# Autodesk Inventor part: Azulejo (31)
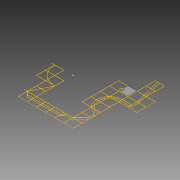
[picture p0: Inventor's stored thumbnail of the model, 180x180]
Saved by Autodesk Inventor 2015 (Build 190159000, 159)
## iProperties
Created: 2015-04
Part Number: Azulejo (31)
Material: Genérico
Document SubType Name: Modeling
Designer: Felipe
Density: 1 g/cm^3
Appearance: Padrão
Author: Felipe
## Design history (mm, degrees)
sketch "Sketch1"
  geometry: L1 (-1510, -7490)-(-1510, -6010); L2 (-3010, -1490)-(-3010, -10); L3 (-2990, 10)-(-1510, 10); L4 (-1510, -10)-(-2990, -10); L5 (-1510, -1490)-(-1510, -10); L6 (-1490, -10)-(-1490, -1490); L7 (-1490, -1490)-(-10, -1490); L8 (-10, -1510)-(-1490, -1510); L9 (-10, -2990)-(-10, -1510); L10 (-10, -5990)-(-10, -4510); L11 (-1490, -7490)-(-10, -7490); L12 (4490, -6010)-(3010, -6010); L13 (10, -1510)-(10, -2990); L14 (10, -3010)-(10, -4490); L15 (10, -4510)-(10, -5990); L16 (10, -5990)-(1490, -5990); L17 (1490, -6010)-(10, -6010); L18 (10, -7490)-(1490, -7490); L19 (1510, -5990)-(2990, -5990); L20 (2990, -6010)-(1510, -6010); L21 (1510, -7490)-(2990, -7490); L22 (4490, 1510)-(4490, 2990); L23 (4490, 10)-(4490, 1490); L24 (4490, -1490)-(4490, -10); L25 (4490, -2990)-(4490, -1510); L26 (3010, -5990)-(4490, -5990); L27 (3010, -7490)-(4490, -7490); L28 (4510, 3010)-(5990, 3010); L29 (5990, 2990)-(4510, 2990); L30 (4510, 2990)-(4510, 1510); L31 (4510, 1510)-(5990, 1510); L32 (5990, 1510)-(5990, 1740.185); L33 (5990, 1760.2)-(5990, 2259.8); L34 (5990, 2279.815)-(5990, 2990); L35 (5990, 1490)-(4510, 1490); L36 (4510, 1490)-(4510, 10); L37 (4510, 10)-(5990, 10); L38 (5990, 10)-(5990, 1490); L39 (5975.983, -10)-(4510, -10); L40 (4510, -10)-(4510, -1490); L41 (5990, -1510)-(5782.897, -1510); L42 (5782.897, -1510)-(5688.66, -1510); L43 (5668.66, -1510)-(5482.895, -1510); L44 (5482.895, -1510)-(5388.656, -1510); L45 (5368.656, -1510)-(4510, -1510); L46 (4510, -1510)-(4510, -2990); L47 (4510, -2990)-(5975.983, -2990); L48 (5990, -2975.728)-(5990, -2837.377); L49 (5990, -2837.377)-(5990, -2536.247); L50 (5990, -2500.476)-(5990, -2317.632); L51 (5990, -2317.632)-(5990, -1510); L52 (5990, -3010)-(4510, -3010); L53 (5990, -4490)-(5990, -3010); L54 (4510, -5990)-(5990, -5990); L55 (5990, -5990)-(5990, -4510); L56 (4510, -7490)-(5990, -7490); L57 (5990, -7490)-(5990, -6310); L58 (5990, -6290)-(5990, -6010); L59 (7490, 4510)-(7490, 5990); L60 (6010, 3010)-(7490, 3010); L61 (7490, 3010)-(7490, 4490); L62 (7490, 2990)-(6010, 2990); L63 (6010, 2990)-(6010, 2279.815); L64 (6010, 2259.8)-(6010, 1760.2)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; A1 r 250 centre (6000, 2010) between (5990, 2259.8) and (5990, 1760.2); A2 r 250 centre (6000, 2010) between (6010, 1760.2) and (6010, 2259.8); A3 r 270 centre (6000, 2010) between (5990, 2279.815) and (5990, 1740.185); A4 r 270 centre (6000, 2010) between (6010, 1740.185) and (6010, 2279.815); A5 r 3010.017 centre (0, 0) between (-1490, -2615.358) and (-346.554, -2990); A6 r 2990.017 centre (0, 0) between (-1490, -2592.316) and (-10, -2990); A7 r 3010.017 centre (0, 0) between (-2603.863, -1510) and (-1510, -2603.863); A8 r 2990.017 centre (0, 0) between (-2580.717, -1510) and (-1510, -2580.717); A9 r 3010.017 centre (0, 0) between (-2990, -346.554) and (-2615.358, -1490); A10 r 2990.017 centre (0, 0) between (-2990, -10) and (-2592.316, -1490); A11 r 2131.367 centre (7500, -1500) between (7490, 631.344) and (6010, 24.017); A12 r 2131.367 centre (7500, -1500) between (5975.983, -10) and (5368.656, -1490); A13 r 2131.367 centre (7500, -1500) between (5368.656, -1510) and (5975.983, -2990); A14 r 2131.367 centre (7500, -1500) between (6010, -3024.017) and (7190, -3608.703); A15 r 1831.367 centre (7500, -1500) between (7490.321, 331.342) and (6463.753, 10); A16 r 1831.367 centre (7500, -1500) between (6435.196, -10) and (6010, -435.196); A17 r 1831.367 centre (7500, -1500) between (5990, -463.753) and (5668.66, -1490); A18 r 1831.367 centre (7500, -1500) between (5668.66, -1510) and (5990, -2536.247); A19 r 1831.367 centre (7500, -1500) between (6010, -2564.804) and (6435.196, -2990); A20 r 1831.367 centre (7500, -1500) between (6463.753, -3010) and (7490, -3331.34); A21 r 2111.367 centre (7500, -1500) between (7490.047, 611.344) and (6024.272, 10); A22 r 2111.367 centre (7500, -1500) between (5990, -24.272) and (5388.656, -1490); A23 r 2111.367 centre (7500, -1500) between (5388.656, -1510) and (5990, -2975.728); A24 r 2111.367 centre (7500, -1500) between (6024.272, -3010) and (7210, -3591.357); A25 r 1811.367 centre (7500, -1500) between (7490.374, 311.342) and (6499.524, 10); A26 r 1811.367 centre (7500, -1500) between (6469.975, -10) and (6010, -469.975); A27 r 1811.367 centre (7500, -1500) between (5990, -499.524) and (5688.66, -1490); A28 r 1811.367 centre (7500, -1500) between (5688.66, -1510) and (5990, -2500.476); A29 r 1811.367 centre (7500, -1500) between (6010, -2530.025) and (6469.975, -2990); A30 r 1811.367 centre (7500, -1500) between (6499.524, -3010) and (7490, -3311.34); A31 r 449.871 centre (7499.449, -4060.672) between (7510, -4510.419) and (7521.546, -4510); 9 further points
  constraints: 698 end point, 64 point on circle, 31 centre point, 11 point on line, 1 other
extrude "Extrusion1" new body sketch "Sketch1" distance "d0" = 60; taper "d1" = 0 deg
extrude "Extrusion2" new body sketch "Sketch1" distance "d2" = 60; taper "d3" = 0 deg
body "Solid1"
body "Solid2"
